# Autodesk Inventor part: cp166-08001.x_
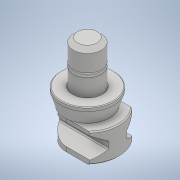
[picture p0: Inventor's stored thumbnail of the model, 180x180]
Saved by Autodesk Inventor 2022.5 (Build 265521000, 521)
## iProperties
Created: 2019-12
Part Number: cp166-08001.x_
Material: 一般
Document SubType Name: Modeling
Designer: ImaoCorp
Density: 1 g/cm^3
Appearance: 既定
Sending System: SOLIDWORKS 2018-2018316
MC: AMD64
MC_MODEL: Intel64 Family 6 Model 60 Stepping 3, GenuineIntel
OS: Windows_NT
FRU: Parasolid Version 30.0, build 310,  6- 8-2018
FORMAT: text
GUISE: transmit
KEY: cp166-08001
FILE: cp166-08001.x_t
DATE: Thu Dec 26 10:15:08 2019
Author: ImaoCorp
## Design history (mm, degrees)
feature "Base1"
node "ソリッド1"
